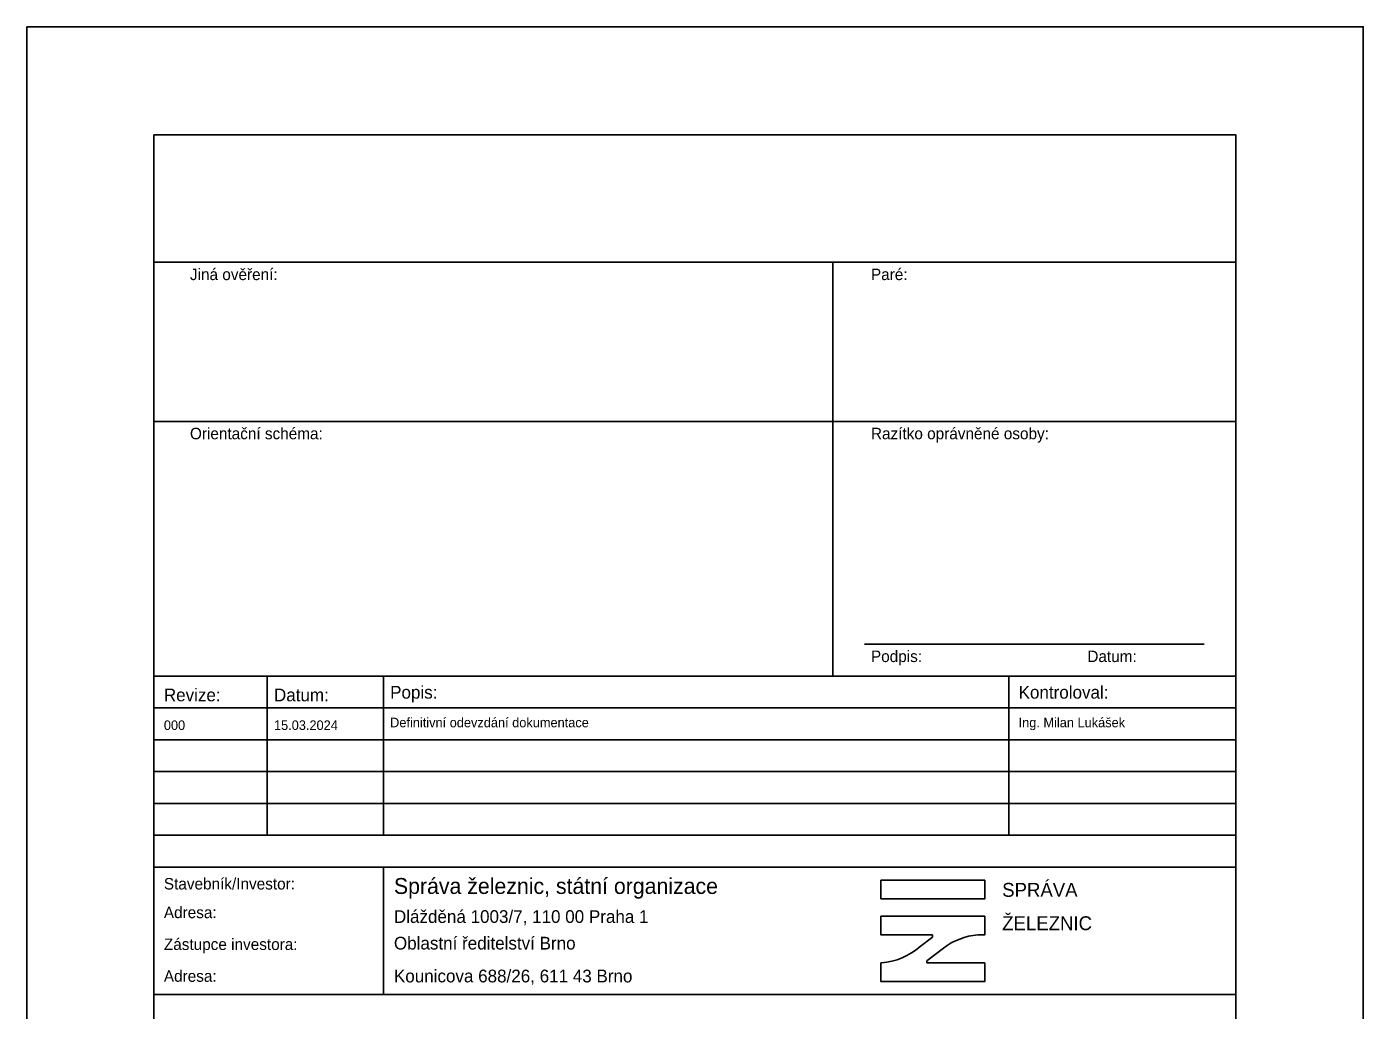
# Model space of a CAD drawing. Extents: x -147.1 to -126.1, y 467.3 to 497.
# Drawn here: x -147.06 to -126.06, y 481.6 to 497.05 of the extents above; entities that cross this region are included whole.
import ezdxf

# ---------------------------------------------------------------- set-up
doc = ezdxf.new("R2010")
doc.units = 0
for name, color, linetype in [('Default', 7, 'Continuous'), ('pomocná - netisk 2', 7, 'Continuous'), ('Rozpiska_Logo', 7, 'Continuous'), ('Rozpiska_pola_3', 7, 'Continuous'), ('Rozpiska_pole_1', 7, 'Continuous'), ('Rozpiska_pole_2', 7, 'Continuous'), ('Rozpiska_pole_4', 7, 'Continuous'), ('Rozpiska_pole_5', 7, 'Continuous'), ('Rozpiska_pole_6', 7, 'Continuous')]:
    doc.layers.add(name, color=color, linetype=linetype)

msp = doc.modelspace()

# ---------------------------------------------------------------- linework, layer by layer
at = {"layer": 'Default'}
msp.add_line((-134.398, 486.849), (-134.398, 493.349), dxfattribs=at)
at = {"layer": 'pomocná - netisk 2'}
msp.add_lwpolyline([(-147.063, 497.049), (-126.063, 497.049), (-126.063, 467.349), (-147.063, 467.349)], close=True, dxfattribs=at)
at = {"layer": 'Rozpiska_Logo'}
for p, q in [((-133.023, 482.602), (-132.829, 482.748)), ((-132.829, 482.748), (-132.829, 482.783)), ((-132.66, 482.575), (-132.921, 482.373)), ((-132.921, 482.373), (-132.921, 482.342))]:
    msp.add_line(p, q, dxfattribs=at)
msp.add_lwpolyline([(-133.641, 483.64), (-132.011, 483.64), (-132.011, 483.347), (-133.641, 483.347)], close=True, dxfattribs=at)
for points in [[(-132.829, 482.783), (-133.641, 482.783), (-133.641, 483.076), (-132.011, 483.076), (-132.011, 482.783), (-132.118, 482.783)], [(-132.921, 482.342), (-132.011, 482.342), (-132.011, 482.049), (-133.641, 482.049), (-133.641, 482.342), (-133.634, 482.342)]]:
    msp.add_lwpolyline(points, dxfattribs=at)
for centre, radius, start, end in [((-133.719, 483.391), 1.052, 274.6014, 311.4254), ((-132.044, 481.781), 1.004, 94.2142, 127.7808)]:
    msp.add_arc(centre, radius, start, end, dxfattribs=at)
at = {"layer": 'Rozpiska_pola_3'}
msp.add_line((-133.898, 487.349), (-128.563, 487.349), dxfattribs=at)
at = {"layer": 'Rozpiska_pole_1'}
msp.add_lwpolyline([(-145.063, 495.349), (-128.063, 495.349), (-128.063, 468.849), (-145.063, 468.849)], close=True, dxfattribs=at)
at = {"layer": 'Rozpiska_pole_2'}
for points in [[(-145.063, 493.349), (-134.398, 493.349), (-134.398, 490.849), (-145.063, 490.849)], [(-134.398, 493.349), (-128.063, 493.349), (-128.063, 490.849), (-134.398, 490.849)], [(-145.063, 490.849), (-134.398, 490.849), (-134.398, 486.849), (-145.063, 486.849)], [(-128.063, 490.849), (-134.398, 490.849), (-134.398, 486.849), (-128.063, 486.849)]]:
    msp.add_lwpolyline(points, close=True, dxfattribs=at)
at = {"layer": 'Rozpiska_pole_4'}
for p, q in [((-143.285, 484.349), (-143.285, 486.849)), ((-141.458, 484.349), (-141.458, 486.849)), ((-131.633, 484.349), (-131.633, 486.849)), ((-145.063, 486.349), (-128.063, 486.349)), ((-145.063, 485.849), (-128.063, 485.849)), ((-145.063, 485.349), (-128.063, 485.349)), ((-145.063, 484.849), (-128.063, 484.849))]:
    msp.add_line(p, q, dxfattribs=at)
msp.add_lwpolyline([(-145.063, 486.849), (-128.063, 486.849), (-128.063, 484.349), (-145.063, 484.349)], close=True, dxfattribs=at)
at = {"layer": 'Rozpiska_pole_5'}
msp.add_line((-141.458, 481.849), (-141.458, 483.849), dxfattribs=at)
msp.add_lwpolyline([(-145.063, 483.849), (-128.063, 483.849), (-128.063, 481.849), (-145.063, 481.849)], close=True, dxfattribs=at)

# ---------------------------------------------------------------- texts
at = {"layer": 'Rozpiska_pola_3'}
for s, p in [('Paré:', (-133.798, 493.069)), ('Razítko oprávněné osoby:', (-133.798, 490.569)), ('Podpis:', (-133.798, 487.069)), ('Datum:', (-130.398, 487.069))]:
    msp.add_text(s, height=0.18, dxfattribs=at).set_placement(p)
at = {"layer": 'Rozpiska_pole_2'}
for s, p in [('Jiná ověření:', (-144.498, 493.069)), ('Orientační schéma:', (-144.498, 490.569))]:
    msp.add_text(s, height=0.18, dxfattribs=at).set_placement(p)
at = {"layer": 'Rozpiska_pole_4'}
for s, height, p in [('Revize:', 0.2, (-144.908, 486.452)), ('Datum:', 0.2, (-143.178, 486.452)), ('Popis:', 0.2, (-141.353, 486.494)), ('Kontroloval:', 0.2, (-131.478, 486.494)), ('000', 0.15, (-144.908, 486.002)), ('15.03.2024', 0.15, (-143.178, 486.002)), ('Definitivní odevzdání dokumentace', 0.15, (-141.353, 486.044)), ('Ing. Milan Lukášek', 0.15, (-131.478, 486.044))]:
    msp.add_text(s, height=height, dxfattribs=at).set_placement(p)
at = {"layer": 'Rozpiska_pole_5'}
for s, height, p in [('Stavebník/Investor:', 0.18, (-144.908, 483.496)), ('Správa železnic, státní organizace', 0.25, (-141.293, 483.426)), ('Adresa:', 0.18, (-144.908, 483.046)), ('Zástupce investora:', 0.18, (-144.908, 482.546)), ('Adresa:', 0.18, (-144.908, 482.046))]:
    msp.add_text(s, height=height, dxfattribs=at).set_placement(p)
at = {"layer": 'Rozpiska_pole_6'}
for s, height, p in [('SPRÁVA', 0.2183, (-131.736, 483.381)), ('Dlážděná 1003/7, 110 00 Praha 1', 0.2, (-141.293, 482.971)), ('ŽELEZNIC', 0.2183, (-131.736, 482.857)), ('Oblastní ředitelství Brno', 0.2, (-141.293, 482.553)), ('Kounicova 688/26, 611 43 Brno', 0.2, (-141.293, 482.037))]:
    msp.add_text(s, height=height, dxfattribs=at).set_placement(p)

doc.saveas('drawing.dxf')
